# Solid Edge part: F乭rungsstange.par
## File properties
Dokumentum tartalom típus: 0
Last saved by: bmolnar
Revision: 76
Sűrűség: 0,000 kg/m^3
Pontosság: 0,990
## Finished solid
Body 1: solid body, 8 faces, 7 edges, 7 vertices.
  Faces by surface: cone 4, cylinder 2, plane 2
  Edges by curve: circle 7
Bounding box of the edges (mm): 5.000 x 5.000 x 48.000, from (-2.5, -2.5, -24) to (2.5, 2.5, 24).
Cylindrical faces by radius (mm): R1.2295 x1, R2.5 x1
Conical faces (half-angle, radius in mm at the cone's reference point): 45 deg R1.3295 x1, 45 deg R2.25 x1, 45 deg R2.4 x1, 59 deg R0.6148 x1
Planar faces by outward normal: +z 1, -z 1
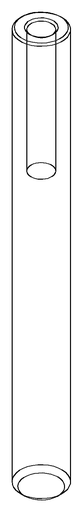
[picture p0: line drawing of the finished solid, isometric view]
